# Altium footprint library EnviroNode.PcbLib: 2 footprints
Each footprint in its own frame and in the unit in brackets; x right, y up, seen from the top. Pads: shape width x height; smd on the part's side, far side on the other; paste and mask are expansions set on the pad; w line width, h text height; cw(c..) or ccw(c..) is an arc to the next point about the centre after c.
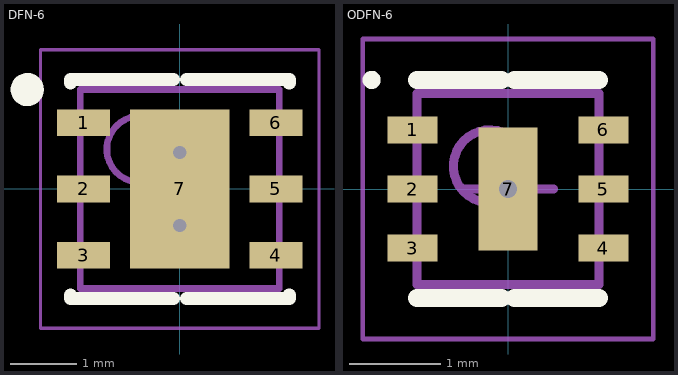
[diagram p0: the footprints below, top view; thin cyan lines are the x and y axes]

## DFN-6 [mm]
height 0.9
pads (7):
  rect 0.8x0.4 smd: 1(-1.45,1) 2(-1.45,0) 3(-1.45,-1) 4(1.45,-1) 5(1.45,0) 6(1.45,1)
  rect 1.5x2.4 smd: 7(0,0)
via 0,-0.55 diameter 0.5 hole 0.2
via 0,0.55 diameter 0.5 hole 0.2
Top Overlay:
  circle w0.25: c-2.3,1.5 r0.125
  lines w0.2: -1.65,-1.6 -1.65,-1.65 -0.1,-1.65 ; -1.65,1.6 -1.65,1.65 -0.1,1.65 ; 0.1,-1.65 1.65,-1.65 1.65,-1.6 ; 0.1,1.65 1.65,1.65 1.65,1.6
Mechanical 13:
  circle w0.1: c-0.6,0.6 r0.5
  lines w0.1: -1.5,-1.5 1.5,-1.5 1.5,1.5 -1.5,1.5 -1.5,-1.5
Mechanical 15:
  lines w0.05: -2.1,-2.1 2.1,-2.1 2.1,2.1 -2.1,2.1 -2.1,-2.1
  lines w0.1: -0.5,0 0.5,0 ; 0,-0.5 0,0.5
3D body: height 0.9, standoff 0, extent -1.5,-1.5 1.5,1.5

## ODFN-6 [mm]
height 0.75
pads (7):
  rect 0.55x0.3 smd: 1(-1.05,0.65) 2(-1.05,0) 3(-1.05,-0.65) 4(1.05,-0.65) 5(1.05,0) 6(1.05,0.65)
  rect 0.65x1.35 smd: 7(0,0)
via 0,0 diameter 0.5 hole 0.2
Top Overlay:
  circle w0.1: c-1.5,1.2 r0.05
  lines w0.2: -1,-1.2 -0.075,-1.2 ; -1,1.2 -0.075,1.2 ; 0.075,-1.2 1,-1.2 ; 0.075,1.2 1,1.2
Mechanical 13:
  circle w0.1: c-0.2,0.25 r0.4
  lines w0.1: -1,-1.05 1,-1.05 1,1.05 -1,1.05 -1,-1.05
Mechanical 15:
  lines w0.05: -1.6,-1.65 1.6,-1.65 1.6,1.65 -1.6,1.65 -1.6,-1.65
  lines w0.1: -0.5,0 0.5,0 ; 0,-0.5 0,0.5
3D body: height 0.75, standoff 0.05, extent -1,-1.05 1,1.05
